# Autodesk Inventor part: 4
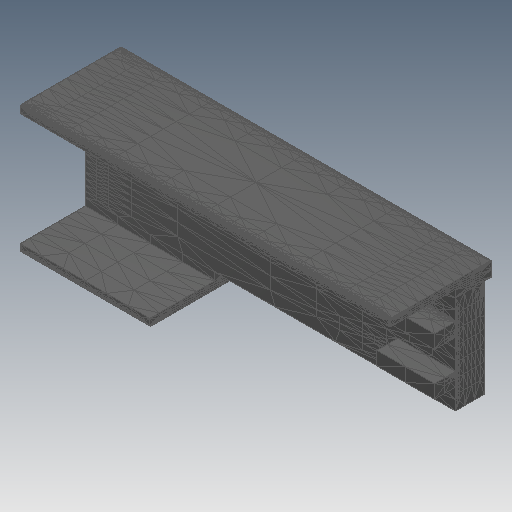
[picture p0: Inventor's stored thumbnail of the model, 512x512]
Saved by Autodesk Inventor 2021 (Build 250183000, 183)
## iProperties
Created: 2026-04
Part Number: 4
Material: Generic
Document SubType Name: Modeling
Designer: JCBG
Density: 1 g/cm^3
Appearance: Default
Author: JCBG
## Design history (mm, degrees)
node "4"
  node "MeshFeature1"
